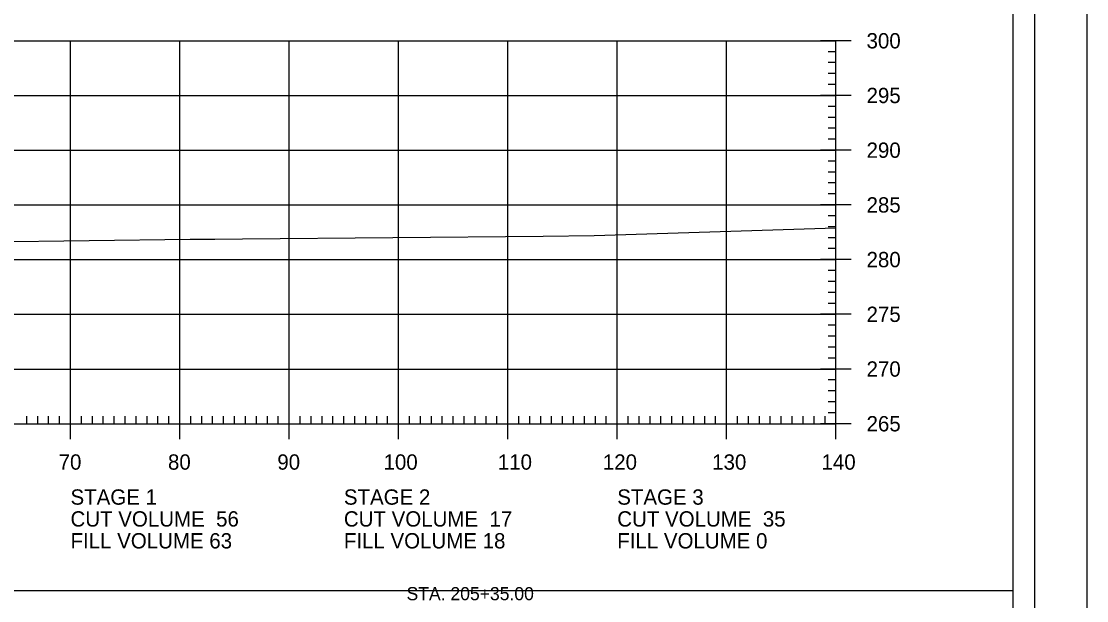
# Model space of a CAD drawing. Extents: x 1368713 to 1370673, y 380279 to 380950.
# Drawn here: x 1370575.1 to 1370672.6, y 380418.2 to 380471.2 of the extents above; entities that cross this region are included whole.
import ezdxf

# ---------------------------------------------------------------- set-up
doc = ezdxf.new("R2010")
doc.units = 0
for name, color, linetype in [('Notes', 7, 'Continuous'), ('R_Axis', 7, 'Continuous'), ('R_Axis Annot', 7, 'Continuous'), ('R_Border', 7, 'Continuous'), ('R_Exist Surface', 7, 'Continuous'), ('R_Grid', 7, 'Continuous'), ('R_No Plot', 7, 'Continuous')]:
    doc.layers.add(name, color=color, linetype=linetype)

msp = doc.modelspace()

# ---------------------------------------------------------------- linework, layer by layer
at = {"layer": 'R_Axis'}
for p, q in [((1370651.029, 380469.416), (1370648.229, 380469.416)), ((1370649.629, 380434.416), (1370649.629, 380469.416)), ((1370649.629, 380468.416), (1370648.929, 380468.416)), ((1370649.629, 380467.416), (1370648.929, 380467.416)), ((1370649.629, 380466.416), (1370648.929, 380466.416)), ((1370649.629, 380465.416), (1370648.929, 380465.416)), ((1370651.029, 380464.416), (1370648.229, 380464.416)), ((1370649.629, 380463.416), (1370648.929, 380463.416)), ((1370649.629, 380462.416), (1370648.929, 380462.416)), ((1370649.629, 380461.416), (1370648.929, 380461.416)), ((1370649.629, 380460.416), (1370648.929, 380460.416)), ((1370651.029, 380459.416), (1370648.229, 380459.416)), ((1370649.629, 380458.416), (1370648.929, 380458.416)), ((1370649.629, 380457.416), (1370648.929, 380457.416)), ((1370649.629, 380456.416), (1370648.929, 380456.416)), ((1370649.629, 380455.416), (1370648.929, 380455.416)), ((1370651.029, 380454.416), (1370648.229, 380454.416)), ((1370649.629, 380453.416), (1370648.929, 380453.416)), ((1370649.629, 380452.416), (1370648.929, 380452.416)), ((1370649.629, 380451.416), (1370648.929, 380451.416)), ((1370649.629, 380450.416), (1370648.929, 380450.416)), ((1370651.029, 380449.416), (1370648.229, 380449.416)), ((1370649.629, 380448.416), (1370648.929, 380448.416)), ((1370649.629, 380447.416), (1370648.929, 380447.416)), ((1370649.629, 380446.416), (1370648.929, 380446.416)), ((1370649.629, 380445.416), (1370648.929, 380445.416)), ((1370651.029, 380444.416), (1370648.229, 380444.416)), ((1370649.629, 380443.416), (1370648.929, 380443.416)), ((1370649.629, 380442.416), (1370648.929, 380442.416)), ((1370649.629, 380441.416), (1370648.929, 380441.416)), ((1370649.629, 380440.416), (1370648.929, 380440.416)), ((1370651.029, 380439.416), (1370648.229, 380439.416)), ((1370649.629, 380438.416), (1370648.929, 380438.416)), ((1370649.629, 380437.416), (1370648.929, 380437.416)), ((1370649.629, 380436.416), (1370648.929, 380436.416)), ((1370575.629, 380434.416), (1370575.629, 380435.116)), ((1370576.629, 380434.416), (1370576.629, 380435.116)), ((1370577.629, 380434.416), (1370577.629, 380435.116)), ((1370578.629, 380434.416), (1370578.629, 380435.116)), ((1370579.629, 380433.016), (1370579.629, 380435.816)), ((1370580.629, 380434.416), (1370580.629, 380435.116)), ((1370581.629, 380434.416), (1370581.629, 380435.116)), ((1370582.629, 380434.416), (1370582.629, 380435.116)), ((1370583.629, 380434.416), (1370583.629, 380435.116)), ((1370584.629, 380434.416), (1370584.629, 380435.116)), ((1370585.629, 380434.416), (1370585.629, 380435.116)), ((1370586.629, 380434.416), (1370586.629, 380435.116)), ((1370587.629, 380434.416), (1370587.629, 380435.116)), ((1370588.629, 380434.416), (1370588.629, 380435.116)), ((1370589.629, 380433.016), (1370589.629, 380435.816)), ((1370590.629, 380434.416), (1370590.629, 380435.116)), ((1370591.629, 380434.416), (1370591.629, 380435.116)), ((1370592.629, 380434.416), (1370592.629, 380435.116)), ((1370593.629, 380434.416), (1370593.629, 380435.116)), ((1370594.629, 380434.416), (1370594.629, 380435.116)), ((1370595.629, 380434.416), (1370595.629, 380435.116)), ((1370596.629, 380434.416), (1370596.629, 380435.116)), ((1370597.629, 380434.416), (1370597.629, 380435.116)), ((1370598.629, 380434.416), (1370598.629, 380435.116)), ((1370599.629, 380433.016), (1370599.629, 380435.816)), ((1370600.629, 380434.416), (1370600.629, 380435.116)), ((1370601.629, 380434.416), (1370601.629, 380435.116)), ((1370602.629, 380434.416), (1370602.629, 380435.116)), ((1370603.629, 380434.416), (1370603.629, 380435.116)), ((1370604.629, 380434.416), (1370604.629, 380435.116)), ((1370605.629, 380434.416), (1370605.629, 380435.116)), ((1370606.629, 380434.416), (1370606.629, 380435.116)), ((1370607.629, 380434.416), (1370607.629, 380435.116)), ((1370608.629, 380434.416), (1370608.629, 380435.116)), ((1370609.629, 380433.016), (1370609.629, 380435.816)), ((1370610.629, 380434.416), (1370610.629, 380435.116)), ((1370611.629, 380434.416), (1370611.629, 380435.116)), ((1370612.629, 380434.416), (1370612.629, 380435.116)), ((1370613.629, 380434.416), (1370613.629, 380435.116)), ((1370614.629, 380434.416), (1370614.629, 380435.116)), ((1370615.629, 380434.416), (1370615.629, 380435.116)), ((1370616.629, 380434.416), (1370616.629, 380435.116)), ((1370617.629, 380434.416), (1370617.629, 380435.116)), ((1370618.629, 380434.416), (1370618.629, 380435.116)), ((1370619.629, 380433.016), (1370619.629, 380435.816)), ((1370620.629, 380434.416), (1370620.629, 380435.116)), ((1370621.629, 380434.416), (1370621.629, 380435.116)), ((1370622.629, 380434.416), (1370622.629, 380435.116)), ((1370623.629, 380434.416), (1370623.629, 380435.116)), ((1370624.629, 380434.416), (1370624.629, 380435.116)), ((1370625.629, 380434.416), (1370625.629, 380435.116)), ((1370626.629, 380434.416), (1370626.629, 380435.116)), ((1370627.629, 380434.416), (1370627.629, 380435.116)), ((1370628.629, 380434.416), (1370628.629, 380435.116)), ((1370629.629, 380433.016), (1370629.629, 380435.816)), ((1370630.629, 380434.416), (1370630.629, 380435.116)), ((1370631.629, 380434.416), (1370631.629, 380435.116)), ((1370632.629, 380434.416), (1370632.629, 380435.116)), ((1370633.629, 380434.416), (1370633.629, 380435.116)), ((1370634.629, 380434.416), (1370634.629, 380435.116)), ((1370635.629, 380434.416), (1370635.629, 380435.116)), ((1370636.629, 380434.416), (1370636.629, 380435.116)), ((1370637.629, 380434.416), (1370637.629, 380435.116)), ((1370638.629, 380434.416), (1370638.629, 380435.116)), ((1370639.629, 380433.016), (1370639.629, 380435.816)), ((1370640.629, 380434.416), (1370640.629, 380435.116)), ((1370641.629, 380434.416), (1370641.629, 380435.116)), ((1370642.629, 380434.416), (1370642.629, 380435.116)), ((1370643.629, 380434.416), (1370643.629, 380435.116)), ((1370644.629, 380434.416), (1370644.629, 380435.116)), ((1370645.629, 380434.416), (1370645.629, 380435.116)), ((1370646.629, 380434.416), (1370646.629, 380435.116)), ((1370647.629, 380434.416), (1370647.629, 380435.116)), ((1370648.629, 380434.416), (1370648.629, 380435.116)), ((1370649.629, 380435.416), (1370648.929, 380435.416)), ((1370649.629, 380433.016), (1370649.629, 380435.816)), ((1370369.629, 380434.416), (1370649.629, 380434.416)), ((1370651.029, 380434.416), (1370648.229, 380434.416))]:
    msp.add_line(p, q, dxfattribs=at)
at = {"layer": 'R_Border'}
msp.add_line((1370667.809, 380314.416), (1370667.809, 380519.876), dxfattribs=at)
at = {"layer": 'R_Exist Surface'}
msp.add_lwpolyline([(1370562.825, 380450.932), (1370590.58, 380451.286), (1370592.839, 380451.288), (1370595.366, 380451.317), (1370622.853, 380451.542), (1370627.505, 380451.621), (1370649.629, 380452.318)], dxfattribs=at)
at = {"layer": 'R_Grid'}
for p, q in [((1370369.629, 380469.416), (1370649.629, 380469.416)), ((1370579.629, 380434.416), (1370579.629, 380469.416)), ((1370589.629, 380434.416), (1370589.629, 380469.416)), ((1370599.629, 380434.416), (1370599.629, 380469.416)), ((1370609.629, 380434.416), (1370609.629, 380469.416)), ((1370619.629, 380434.416), (1370619.629, 380469.416)), ((1370629.629, 380434.416), (1370629.629, 380469.416)), ((1370639.629, 380434.416), (1370639.629, 380469.416)), ((1370649.629, 380434.416), (1370649.629, 380469.416)), ((1370369.629, 380464.416), (1370649.629, 380464.416)), ((1370369.629, 380459.416), (1370649.629, 380459.416)), ((1370369.629, 380454.416), (1370649.629, 380454.416)), ((1370369.629, 380449.416), (1370649.629, 380449.416)), ((1370369.629, 380444.416), (1370649.629, 380444.416)), ((1370369.629, 380439.416), (1370649.629, 380439.416)), ((1370369.629, 380434.416), (1370649.629, 380434.416))]:
    msp.add_line(p, q, dxfattribs=at)
at = {"layer": 'R_No Plot'}
for points in [[(1370339.221, 380523.77), (1370672.561, 380523.77), (1370672.561, 380310.433), (1370339.221, 380310.433)], [(1370665.809, 380419.146), (1370353.629, 380419.146), (1370353.629, 380517.876), (1370603.169, 380517.876), (1370603.169, 380507.996), (1370620.709, 380507.996), (1370644.809, 380507.996), (1370644.809, 380485.663), (1370665.809, 380485.663)], [(1370353.629, 380517.876), (1370603.169, 380517.876), (1370603.169, 380507.996), (1370620.709, 380507.996), (1370644.809, 380507.996), (1370644.809, 380485.663), (1370665.809, 380485.663), (1370665.809, 380316.416), (1370353.629, 380316.416)]]:
    msp.add_lwpolyline(points, close=True, dxfattribs=at)

# ---------------------------------------------------------------- texts
at = {"layer": 'Notes'}
msp.add_text('STA. 205+35.00', height=1.2, dxfattribs=at).set_placement((1370610.362, 380418.286))
at = {"layer": 'R_Axis Annot'}
for s, p in [('300', (1370652.429, 380468.716)), ('295', (1370652.429, 380463.716)), ('290', (1370652.429, 380458.716)), ('285', (1370652.429, 380453.716)), ('280', (1370652.429, 380448.716)), ('275', (1370652.429, 380443.716)), ('270', (1370652.429, 380438.716)), ('265', (1370652.429, 380433.716)), ('70', (1370578.543, 380430.216)), ('80', (1370588.543, 380430.216)), ('90', (1370598.543, 380430.216)), ('100', (1370608.257, 380430.216)), ('110', (1370618.709, 380430.216)), ('120', (1370628.312, 380430.216)), ('130', (1370638.312, 380430.216)), ('140', (1370648.312, 380430.216)), ('STAGE 1', (1370579.629, 380427.016)), ('STAGE 2', (1370604.629, 380427.016)), ('STAGE 3', (1370629.629, 380427.016)), ('CUT VOLUME  56', (1370579.629, 380425.016)), ('CUT VOLUME  17', (1370604.629, 380425.016)), ('CUT VOLUME  35', (1370629.629, 380425.016)), ('FILL VOLUME 63', (1370579.629, 380423.016)), ('FILL VOLUME 18', (1370604.629, 380423.016)), ('FILL VOLUME 0', (1370629.629, 380423.016))]:
    msp.add_text(s, height=1.4, dxfattribs=at).set_placement(p)

doc.saveas('drawing.dxf')
